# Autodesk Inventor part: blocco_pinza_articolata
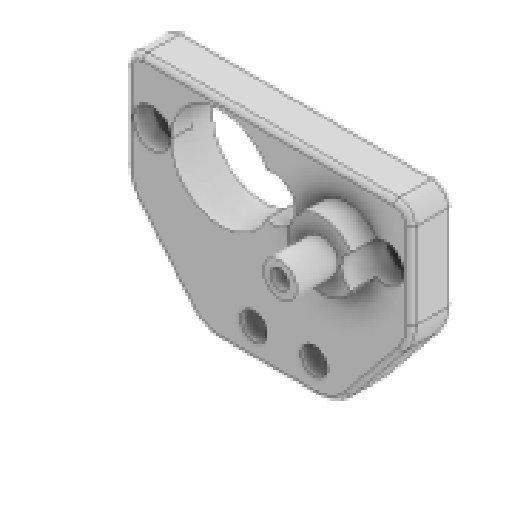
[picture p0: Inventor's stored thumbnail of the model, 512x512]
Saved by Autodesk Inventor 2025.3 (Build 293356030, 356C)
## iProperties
Created: 2026-03
Part Number: blocco_pinza_articolata
Material: Generico
Document SubType Name: Modeling
Designer: R5800u
Density: 1 g/cm^3
Appearance: Default
Author: R5800u
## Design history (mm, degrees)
sketch "Schizzo1"
  geometry: L1 (0, 0)-(0, 11.705) reference; L2 (0, 0)-(6.476, 0) reference; L3 (-17, 7)-(17, 7); L4 (17, 7)-(17, -7); L5 (17, -7)-(-17, -7); L6 (-17, -7)-(-17, 7); L7 (0, -7)-(-8, -7); L8 (-8, -7)-(-8, -18); L9 (-8, -18)-(0, -18); L10 (0, -18)-(0, -7); L11 (0, -7)-(8, -7); L12 (8, -7)-(8, -18); L13 (8, -18)-(0, -18); L14 (0, -18)-(0, -7); L15 (-17, -7)-(-8, -18); L16 (17, -7)-(8, -18); A1 r 5.8 centre (-5.65, 0) between (-0.341, 2.336) and (-0.341, -2.336) reference; A2 r 2.5 centre (0.55, 0) between (-0.341, -2.336) and (-0.341, 2.336) reference; A3 r 6 centre (-5.65, 0) between (-0.235, 2.583) and (-0.235, -2.583); A4 r 2.7 centre (0.55, 0) between (-0.235, -2.583) and (-0.235, 2.583); 6 further points
  constraints: 32 end point, 6 parallel, 5 horizontal, 4 point on circle, 3 perpendicular, 2 centre point, 2 vertical, 1 midpoint, 1 point on line, 6 other
  dimensions: "d0" = 34 distance of L4.end L5.end; "d1" = 14 distance of L3.end L4.end; "d2" = 0.2 radial gap between concentric circles of A1 A3; "d18" = 8 distance of L9.end L8.end; "d19" = 11 distance of L8.end L7.end; "d20" = 8 distance of L12.end L13.end
  node "Riferimento1"
  node "Riferimento2"
node "Piano di lavoro1"
extrude "Estrusione1" new body sketch "Schizzo1" stored distance "d3" = 10; taper "d4" = 0 deg
sketch "Schizzo2"
  geometry: A1 r 1 centre (30.9, 7) between (31.7, 7.6) and (31.7, 6.4) reference; A2 r 1 centre (3.1, 7) between (2.3, 6.4) and (2.3, 7.6) reference; 1 further point
hole "Foro1" sketch "Schizzo2" at (30.9, 7), (3.1, 7) diameter "d5" = 2.7; stored, may be unused: countersink angle "d9" = 90 deg, drill point angle "d11" = 118 deg; dims "d6" = 6, "d7" = 4.5, "d8" = 2.5, "d10" = 8
sketch "Schizzo3"
  geometry: C1 r 2 at (26.35, 7); A1 r 6.25 centre (26.35, 7) between (27.71, 0.9) and (28.34, 1.075) reference; 1 further point
  constraints: 1 centre point, 1 coincident
  dimensions: "d12" = 4 diameter of C1
extrude "Estrusione2" join sketch "Schizzo3" distance "d13" = 8; taper "d14" = 0 deg
sketch "Schizzo4"
  geometry: C1 r 2 at (26.35, 7) reference; C2 r 4 at (26.35, 7); C3 r 2.25 at (30.9, 7) reference; 3 further points
  constraints: 1 centre point, 1 coincident
  dimensions: "d15" = 8 diameter of C2
node "Piano di lavoro2"
extrude "Estrusione3" join sketch "Schizzo4" stored distance "d16" = 9; taper "d17" = 0 deg
sketch "Schizzo5"
  geometry: L1 (25, -25)-(9, -25) reference; L2 (26.35, -7)-(11.35, -7); L3 (18.85, -7)-(18.85, -21.4); L4 (22.45, -21.4)-(18.85, -21.4); L5 (18.85, -21.4)-(15.25, -21.4); C1 r 2 at (26.35, -7) reference; C2 r 2.25 at (11.35, -7) reference
  constraints: 8 end point, 3 horizontal, 1 midpoint, 1 vertical
  dimensions: "d29" = 14.4 distance of L3.start L3.end; "d31" = 3.6 distance of L3.end L5.end; "d34" = 3.6 distance of L4.start L3.end
hole "Foro2" sketch "Schizzo5" at (15.25, -21.4), (22.45, -21.4) diameter "d22" = 3.2; stored, may be unused: countersink angle "d26" = 90 deg, drill point angle "d28" = 118 deg; dims "d23" = 6, "d24" = 6.5, "d25" = 3.4, "d27" = 8
fillet "Raccordo2" dims "d33" = 2
fillet "Raccordo3" dims "d35" = 5
sketch "Schizzo6"
  geometry: C1 r 2 at (-9.35, 0) reference; 1 further point
hole "Foro3" sketch "Schizzo6" at (-9.35, 0) diameter "d37" = 2.2; stored, may be unused: countersink angle "d41" = 90 deg, drill point angle "d43" = 118 deg; dims "d38" = 6, "d39" = 4.4, "d40" = 3.5, "d42" = 8
node "Solido1"
node "Riferimento3"
node "Riferimento4"
node "Riferimento5"
node "Riferimento6"
node "Linea chiusa proiettata1"
other parameters: "d30" = 4
